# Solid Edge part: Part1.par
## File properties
Author: Dan
Template: Normal.par
Last saved by: Dan
Revision: 1
Application: Solid Edge
Density: 0 kg/mm^3
Accuracy: 0.99
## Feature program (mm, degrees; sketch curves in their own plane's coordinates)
sketch for "unnamed Protrusion 1" #1 plane through (0, 0, 0) normal (0, 0, 1) x-axis (1, 0, 0)
  circle centre (0, 0) radius 51.8628
sketch for "unnamed Protrusion 1" #2 plane through (0, 0, 0) normal (0, 0, 1) x-axis (1, 0, 0)
  circle centre (0, 0) radius 2.5
extrude "unnamed Protrusion 1" add finite 8 along -normal
sketch for "Hole_1" plane through (0, 0, 0) normal (0, 0, 1) x-axis (1, 0, 0)
  hole centre (0, 17.6397) bore radius 2.5
hole "Hole_1" diameter 5 through  VBottomAngle = 118 deg
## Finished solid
Body 1: solid body, 5 faces, 6 edges, 0 vertices.
  Faces by surface: cylinder 3, plane 2
  Edges by curve: circle 6
Bounding box of the edges (mm): 103.726 x 103.726 x 8.000, from (-51.8628, -51.8628, -8) to (51.8628, 51.8628, 0).
Cylindrical faces by radius (mm): R2.5 x2, R51.8628 x1
Planar faces by outward normal: +z 1, -z 1
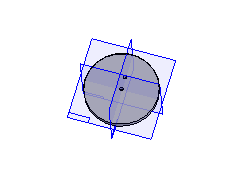
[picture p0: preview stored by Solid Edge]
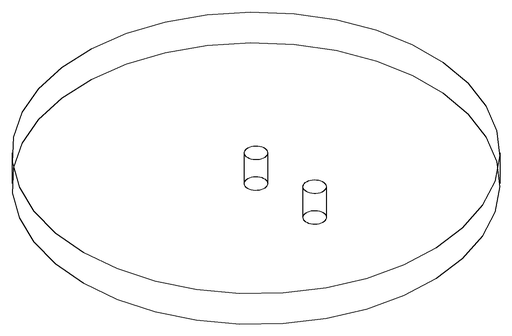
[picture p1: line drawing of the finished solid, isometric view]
